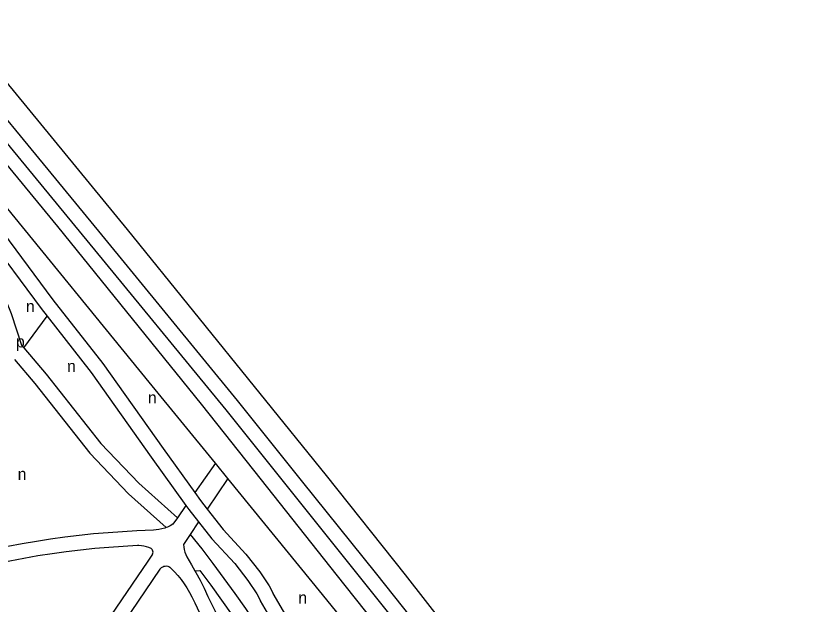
# Model space of a CAD drawing. Extents: x 157155 to 159285, y 385001 to 386651.
# Drawn here: x 158867.8 to 159137.4, y 385603.8 to 385804.1 of the extents above; entities that cross this region are included whole.
import ezdxf

# ---------------------------------------------------------------- set-up
doc = ezdxf.new("R2010")
doc.units = 0
for name, color, linetype in [('BLT_Basislijn', 7, 'Continuous'), ('BLT_Centroide', 7, 'Continuous'), ('BLT_Spoorlijn', 7, 'Continuous')]:
    doc.layers.add(name, color=color, linetype=linetype)

msp = doc.modelspace()

# ---------------------------------------------------------------- linework, layer by layer
at = {"layer": 'BLT_Basislijn'}
for p, q in [((158823.13, 385804.1), (158882.02, 385732.32)), ((158913.32, 385679.35), (158845.43, 385762.34)), ((158882.02, 385732.32), (158931.04, 385671.82)), ((158870.59, 385691.05), (158878.49, 385701.82)), ((158935.84, 385651.74), (158913.32, 385679.35)), ((158931.04, 385671.82), (158951.41, 385646.07)), ((158935.84, 385651.74), (158928.84, 385641.73)), ((158940.11, 385646.51), (158935.84, 385651.74)), ((158940.11, 385646.51), (158933.07, 385636.1)), ((158972.27, 385607.08), (158940.11, 385646.51)), ((158951.41, 385646.07), (158976.88, 385614)), ((158925.81, 385637.39), (158922.88, 385633.2)), ((158922.88, 385633.2), (158921.31, 385630.96)), ((158930.13, 385631.74), (158927.27, 385627.52)), ((158914.72, 385629), (158909.09, 385628.7)), ((158927.27, 385627.52), (158924.97, 385624.1)), ((158912.81, 385618.44), (158895.56, 385593.1)), ((158914.43, 385620.76), (158912.81, 385618.44)), ((158916.94, 385615.62), (158899.7, 385590.29)), ((158928.85, 385615.16), (158930.48, 385615.24)), ((158976.88, 385614), (159002.97, 385581.07)), ((158954.16, 385610.02), (158955.47, 385607.42)), ((158950, 385607.25), (158951.17, 385604.88)), ((159070.44, 385486.48), (158972.27, 385607.08))]:
    msp.add_line(p, q, dxfattribs=at)
for points in [[(158832.9, 385799.5), (158892.09, 385727.58), (158939.39, 385669.9)], [(158851.99, 385747.97), (158861.25, 385733.14), (158880.43, 385707.44), (158897.54, 385685.66), (158918.07, 385656.71), (158928.84, 385641.73)], [(158847.74, 385745.32), (158857.12, 385730.31), (158876.46, 385704.4), (158878.49, 385701.82)], [(158852.61, 385736.09), (158866.23, 385702.76), (158869.83, 385691.95), (158870.59, 385691.05)], [(158878.49, 385701.82), (158893.53, 385682.67), (158914, 385653.8), (158925.81, 385637.39)], [(158870.59, 385691.05), (158878.24, 385682.03), (158896.84, 385658.46), (158909.74, 385644.94), (158922.88, 385633.2)], [(158867.44, 385687.03), (158874.38, 385678.86), (158893.06, 385655.18), (158906.26, 385641.34), (158919.1, 385629.86)], [(158939.39, 385669.9), (159072.13, 385504.06), (159137.44, 385424.52)], [(158928.84, 385641.73), (158930.78, 385639.04), (158933.07, 385636.1)], [(158925.81, 385637.39), (158926.77, 385636.04), (158930.13, 385631.74)], [(158933.07, 385636.1), (158938.45, 385629.22), (158946.21, 385620.83), (158950.99, 385614.77), (158954.16, 385610.02)], [(158919.1, 385629.86), (158918.57, 385629.66), (158917.6, 385629.38), (158916.61, 385629.17), (158915.61, 385629.04), (158914.72, 385629)], [(158921.31, 385630.96), (158920.43, 385630.45), (158919.52, 385630.02), (158919.1, 385629.86)], [(158930.13, 385631.74), (158934.64, 385625.97), (158942.41, 385617.58), (158946.94, 385611.83), (158950, 385607.25)], [(158909.09, 385628.7), (158904.17, 385628.43), (158899.26, 385628.08), (158894.36, 385627.65), (158889.47, 385627.15), (158884.58, 385626.56), (158879.7, 385625.9), (158874.84, 385625.15), (158869.99, 385624.33), (158865.15, 385623.43), (158860.33, 385622.44), (158855.52, 385621.38), (158850.73, 385620.25), (158845.96, 385619.03), (158841.21, 385617.74), (158836.49, 385616.37), (158835.79, 385616.16)], [(158927.27, 385627.52), (158931.16, 385622.57), (158934.99, 385617.57), (158938.76, 385612.52), (158942.46, 385607.42), (158946.09, 385602.28), (158949.66, 385597.09), (158953.16, 385591.86), (158956.6, 385586.58), (158959.97, 385581.26), (158963.27, 385575.9), (158966.5, 385570.5), (158969.66, 385565.05), (158972.76, 385559.57), (158975.78, 385554.05), (158977.75, 385550.36)], [(158924.97, 385624.1), (158925.04, 385623.21), (158925.19, 385622.33), (158925.42, 385621.47), (158925.72, 385620.63), (158926.1, 385619.83)], [(158909.32, 385623.7), (158904.45, 385623.44), (158899.58, 385623.09), (158894.71, 385622.67), (158889.86, 385622.16), (158885.02, 385621.58), (158880.18, 385620.91), (158875.36, 385620.17), (158870.55, 385619.35), (158865.75, 385618.45), (158860.97, 385617.47), (158856.2, 385616.41), (158851.46, 385615.28), (158846.73, 385614.06), (158842.02, 385612.77), (158837.34, 385611.41), (158837.23, 385611.37)], [(158914, 385622.66), (158913.19, 385623.03), (158912.36, 385623.31), (158911.5, 385623.52), (158910.62, 385623.65), (158909.74, 385623.71), (158909.32, 385623.7)], [(158914.43, 385620.76), (158914.55, 385621.09), (158914.59, 385621.44), (158914.55, 385621.79), (158914.44, 385622.12), (158914.25, 385622.41), (158914, 385622.66)], [(158926.1, 385619.83), (158927.7, 385617.18), (158928.85, 385615.16)], [(158916.94, 385615.62), (158917.2, 385615.97), (158917.52, 385616.27), (158917.89, 385616.5), (158918.29, 385616.67), (158918.72, 385616.75), (158919.15, 385616.76), (158919.59, 385616.69), (158919.99, 385616.54), (158920.37, 385616.32), (158920.71, 385616.02)], [(158920.71, 385616.02), (158921.91, 385614.78), (158923.06, 385613.47), (158924.14, 385612.12), (158925.16, 385610.72), (158926.12, 385609.27), (158927.01, 385607.78), (158927.83, 385606.26), (158928.57, 385604.69), (158928.8, 385604.18)], [(158928.85, 385615.16), (158929.19, 385614.56), (158930.61, 385611.91), (158931.96, 385609.22), (158933.27, 385606.42)], [(158930.48, 385615.24), (158934.24, 385610.22), (158937.93, 385605.16), (158941.55, 385600.05), (158945.11, 385594.89), (158948.6, 385589.69), (158952.03, 385584.45), (158955.39, 385579.16), (158958.68, 385573.83), (158961.9, 385568.46), (158965.06, 385563.04), (158968.14, 385557.59), (158971.15, 385552.1), (158973.33, 385548.02)], [(158933.27, 385606.42), (158935.75, 385601.35), (158938.16, 385596.26), (158940.5, 385591.12), (158942.76, 385585.96), (158944.95, 385580.76), (158947.07, 385575.54), (158949.11, 385570.28), (158951.07, 385565), (158952.97, 385559.69), (158954.78, 385554.35), (158956.52, 385548.99), (158957.35, 385546.35)], [(159053.2, 385492.65), (159043.72, 385501.52), (159029.71, 385519.9), (159017.44, 385530.61), (159000.13, 385546.68), (158991.59, 385555.84), (158976.15, 385576.54), (158962.56, 385595.39), (158955.47, 385607.42)], [(158928.8, 385604.18), (158931.26, 385599.15), (158933.65, 385594.09), (158935.98, 385588.99), (158938.22, 385583.86), (158940.4, 385578.69), (158942.5, 385573.5), (158944.52, 385568.27), (158946.47, 385563.02), (158948.35, 385557.74), (158950.15, 385552.44), (158951.87, 385547.11), (158952.57, 385544.88)], [(159010.02, 385530.67), (158996.6, 385543.14), (158987.75, 385552.63), (158972.12, 385573.59), (158958.37, 385592.66), (158951.17, 385604.88)]]:
    msp.add_lwpolyline(points, dxfattribs=at)
at = {"layer": 'BLT_Spoorlijn'}
for points in [[(158836.75, 385802.69), (158895.96, 385730.75)], [(158846.62, 385803.32), (158905.82, 385731.38)], [(158895.96, 385730.75), (158943.26, 385673.07)], [(158905.82, 385731.38), (158973.59, 385647.56)], [(158943.26, 385673.07), (158965.05, 385645.84)], [(158965.05, 385645.84), (158990.67, 385614)], [(158973.59, 385647.56), (159000.46, 385613.69)], [(158990.67, 385614), (159016.99, 385580.91)], [(159000.46, 385613.69), (159025.3, 385581.86)]]:
    msp.add_lwpolyline(points, dxfattribs=at)

# ---------------------------------------------------------------- texts
at = {"layer": 'BLT_Centroide'}
for s, p in [('n', (158871.3, 385703.19)), ('p', (158867.91, 385691.2)), ('n', (158885.31, 385682.8)), ('n', (158912.85, 385672.09)), ('n', (158868.49, 385646.07)), ('n', (158964.1, 385603.98))]:
    msp.add_text(s, height=4, dxfattribs=at).set_placement(p)

doc.saveas('drawing.dxf')
